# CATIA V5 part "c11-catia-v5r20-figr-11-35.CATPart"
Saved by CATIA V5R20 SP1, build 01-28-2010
Part number: Part1
Bounding box of the stored display mesh (mm): x -177 to 59, y -180 to 60, z 0 to 80
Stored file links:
  D:\v5_r20\psrt_files_downloaded\c11\c11-catia-v5r20-figr-11-35.CATPart
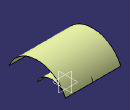
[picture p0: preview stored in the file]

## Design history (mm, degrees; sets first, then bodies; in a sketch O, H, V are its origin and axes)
Set1
  Extrude1: Element1 Sketch1, Lim1 59, Lim2 59, Direction yz-plane
  Scaling1: ToTransfor Extrude1, Reference vertex [face of Extrude1], Ratio 2
Body1 (main body)
  Sketch1 on yz-plane, origin (0, 0, 0), H (0, 1, 0), V (0, 0, 1)
    arc A1 centre (0, -25) radius 65 from (-60, 0) to (60, 0) cw
    point P2 (-60, 0)
    point P3 (60, 0)
    coincidence: P2 H, P3 H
